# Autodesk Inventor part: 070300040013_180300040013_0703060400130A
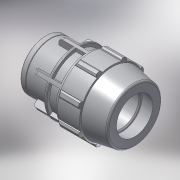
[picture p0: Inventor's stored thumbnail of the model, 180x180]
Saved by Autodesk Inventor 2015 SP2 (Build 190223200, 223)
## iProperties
Created: 2017-02
Part Number: 070300040013_180300040013_0703060400130A
Material: PVC-Piping
Description: PLASSON FEMALE ADAPTOR 40-1.1/4"
Document SubType Name: Modeling
Designer: KIM
Mass: 92.6774 g
Surface Area: 199.44 cm^2
Volume: 66.1981 cm^3
Density: 1.4 g/cm^3
Appearance: Smooth - White
Author: KIM
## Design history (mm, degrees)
derived "07030.ipt"
feature "Solid1::07030.ipt"
tag "TaggingFeature1"
body "Solid1"
other parameters: "d4" = 16.28571, "d5" = 28.5, "d7" = 82, "d9" = 16.28571, "d11" = 3.25714, "d12" = 65.6, "d13" = 120 deg, "d15" = 10 deg, "d16" = 73.8, "d18" = 2, "d19" = 35 deg, "d20" = 17.5 deg, "d21" = 76.26, "d23" = 0, "d25" = 360 deg, "d27" = 1.64, "d34" = 4.1, "d35" = 34.2, "d36" = 0, "d42" = 28.5, "d43" = 2.46, "d46" = 1.2, "d49" = 84, "d51" = 114, "d53" = 0.8, "d55" = 360 deg, "d61" = 25, "d62" = 32, "d63" = 38.952, "d64" = 38, "d65" = 4.1, "d66" = 0.5, "d67" = 1, "d68" = 7.5, "d69" = 59.04, "d70" = 2.05, "E_" = 82, "H_" = 114, "l_" = 84, "l_2" = 25, "Rp_" = 38.952
